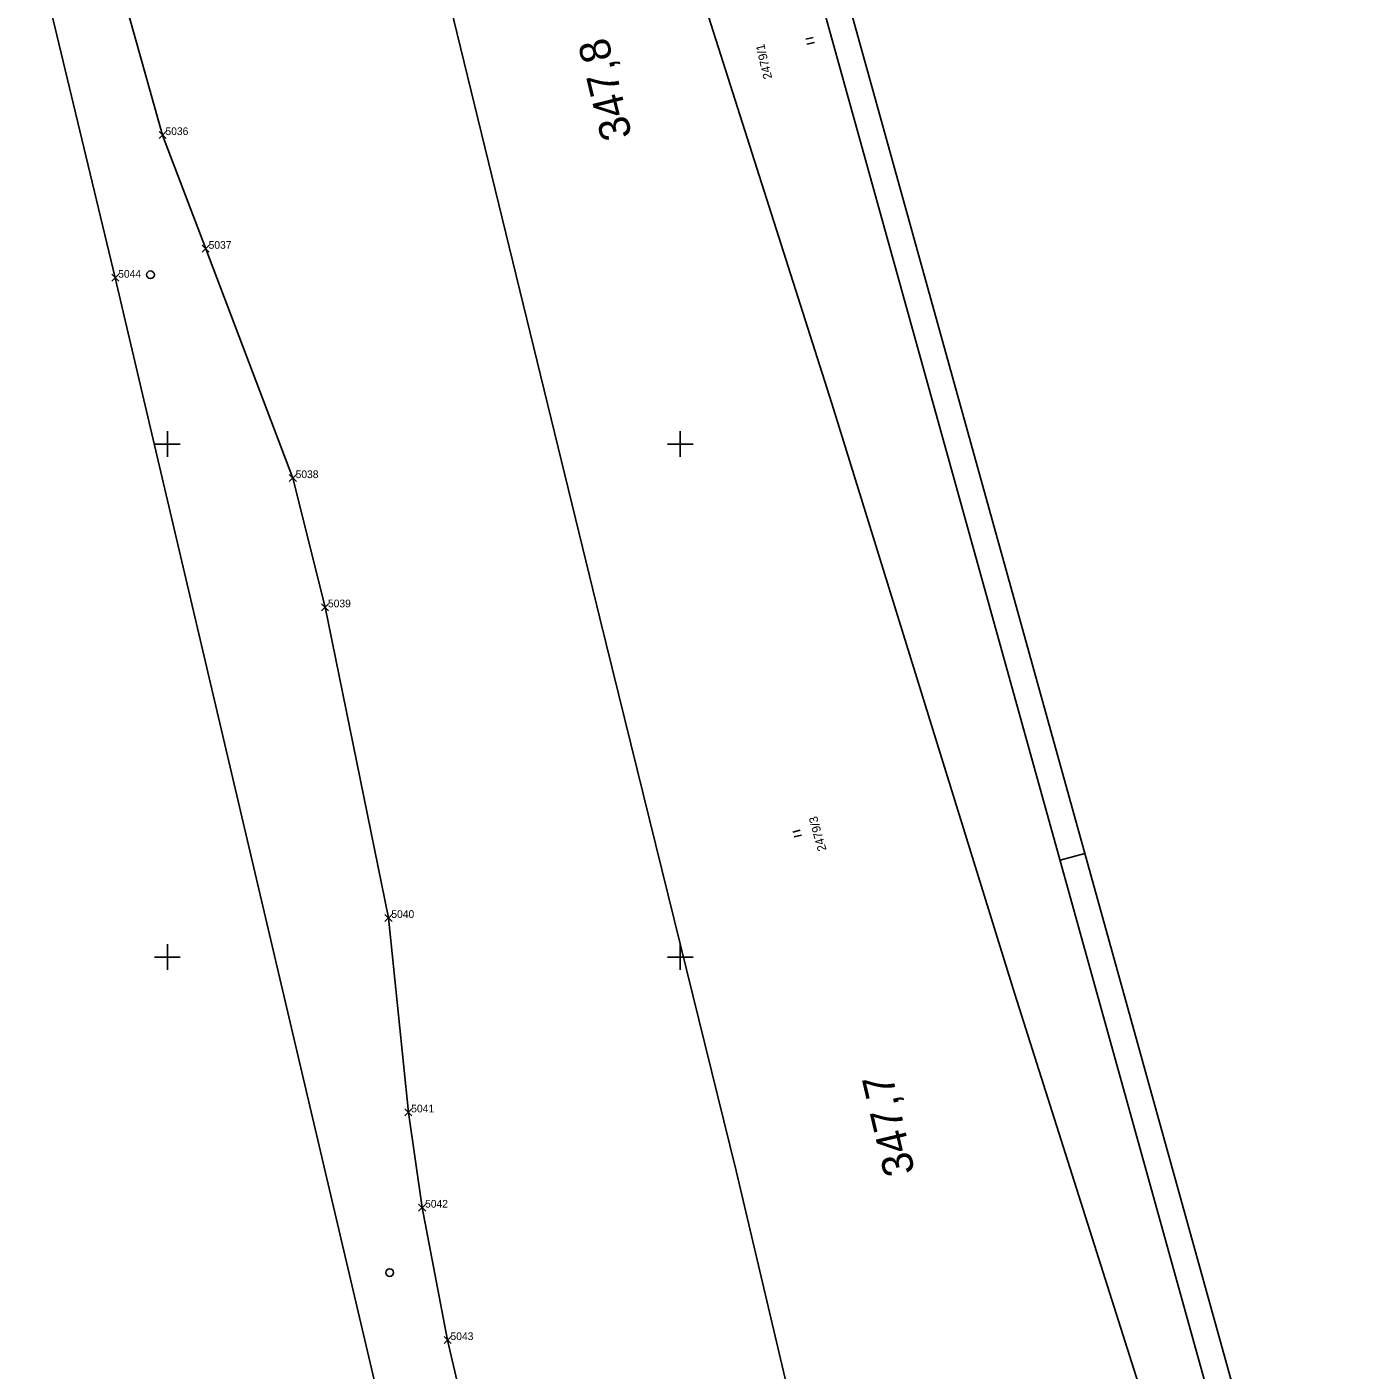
# Model space of a CAD drawing. Extents: x -821172 to -820632, y -1070921 to -1069931.
# Drawn here: x -820763.7 to -820632.5, y -1070790.2 to -1070659.4 of the extents above; entities that cross this region are included whole.
import ezdxf

# ---------------------------------------------------------------- set-up
doc = ezdxf.new("R2010")
doc.units = 0
for name, color, linetype in [('Ram', 7, 'Continuous'), ('Sit', 7, 'Continuous'), ('Sttaniceni a namezniky', 7, 'Continuous'), ('VB_bod_DZ', 7, 'Continuous'), ('Vrstva 52', 7, 'Continuous'), ('Vrstva 53', 7, 'Continuous'), ('Vrstva 55', 7, 'Continuous'), ('Vrstva 57', 7, 'Continuous'), ('Vrstva 59', 7, 'Continuous')]:
    doc.layers.add(name, color=color, linetype=linetype)

msp = doc.modelspace()

# ---------------------------------------------------------------- linework, layer by layer
at = {"layer": 'Ram'}
msp.add_line((-820660.57, -1070739.89), (-820662.98, -1070740.56), dxfattribs=at)
for points in [[(-820857.35, -1070031.72), (-820632.46, -1070841.06)], [(-820859.09, -1070034.8), (-820635.54, -1070839.32), (-820916.88, -1070917.49)]]:
    msp.add_lwpolyline(points, dxfattribs=at)
at = {"layer": 'Sit'}
for p, q in [((-820750, -1070698.75), (-820750, -1070700)), ((-820700, -1070698.75), (-820700, -1070700)), ((-820751.25, -1070700), (-820750, -1070700)), ((-820748.75, -1070700), (-820750, -1070700)), ((-820750, -1070701.25), (-820750, -1070700)), ((-820701.25, -1070700), (-820700, -1070700)), ((-820698.75, -1070700), (-820700, -1070700)), ((-820700, -1070701.25), (-820700, -1070700)), ((-820751.25, -1070750), (-820750, -1070750)), ((-820750, -1070748.75), (-820750, -1070750)), ((-820748.75, -1070750), (-820750, -1070750)), ((-820750, -1070751.25), (-820750, -1070750)), ((-820701.25, -1070750), (-820700, -1070750)), ((-820700, -1070748.75), (-820700, -1070750)), ((-820698.75, -1070750), (-820700, -1070750)), ((-820700, -1070751.25), (-820700, -1070750))]:
    msp.add_line(p, q, dxfattribs=at)
at = {"layer": 'Sttaniceni a namezniky'}
for centre in [(-820751.65, -1070683.5), (-820728.33, -1070780.74)]:
    msp.add_circle(centre, 0.375, dxfattribs=at)
at = {"layer": 'VB_bod_DZ'}
for p, q in [((-820750.81, -1070670.23), (-820750.13, -1070669.55)), ((-820750.13, -1070670.23), (-820750.81, -1070669.55)), ((-820746.61, -1070681.31), (-820745.92, -1070680.62)), ((-820745.92, -1070681.31), (-820746.61, -1070680.62)), ((-820755.43, -1070684.13), (-820754.74, -1070683.45)), ((-820754.74, -1070684.13), (-820755.43, -1070683.45)), ((-820738.12, -1070703.66), (-820737.43, -1070702.97)), ((-820737.43, -1070703.66), (-820738.12, -1070702.97)), ((-820734.97, -1070716.25), (-820734.29, -1070715.56)), ((-820734.29, -1070716.25), (-820734.97, -1070715.56)), ((-820728.79, -1070746.52), (-820728.1, -1070745.84)), ((-820728.1, -1070746.52), (-820728.79, -1070745.84)), ((-820726.86, -1070765.48), (-820726.17, -1070764.79)), ((-820726.17, -1070765.48), (-820726.86, -1070764.79)), ((-820725.51, -1070774.76), (-820724.82, -1070774.07)), ((-820724.82, -1070774.76), (-820725.51, -1070774.07)), ((-820723.02, -1070787.66), (-820722.34, -1070786.97)), ((-820722.34, -1070787.66), (-820723.02, -1070786.97))]:
    msp.add_line(p, q, dxfattribs=at)
at = {"layer": 'Vrstva 52'}
msp.add_lwpolyline([(-820753.84, -1070657.98), (-820750.47, -1070669.89), (-820746.26, -1070680.97), (-820737.78, -1070703.32), (-820734.63, -1070715.91), (-820728.44, -1070746.18), (-820726.51, -1070765.13), (-820725.16, -1070774.41), (-820722.68, -1070787.32), (-820717.67, -1070808.86), (-820710.81, -1070838.96), (-820718.49, -1070840.82), (-820729.1, -1070794.38), (-820755.08, -1070683.79), (-820766.7, -1070635.67)], dxfattribs=at)
at = {"layer": 'Vrstva 53'}
msp.add_lwpolyline([(-820720.44, -1070572.46), (-820743.88, -1070569.76), (-820732.22, -1070617.16), (-820718.37, -1070673.87), (-820707.85, -1070716.96), (-820694.56, -1070770.81), (-820679.24, -1070835.68), (-820677.73, -1070841.82), (-820675.61, -1070850.43)], dxfattribs=at)
at = {"layer": 'Vrstva 55'}
for points in [[(-820720.44, -1070572.46), (-820743.88, -1070569.76), (-820732.22, -1070617.16), (-820718.37, -1070673.87), (-820707.85, -1070716.96), (-820694.56, -1070770.81), (-820679.24, -1070835.68), (-820675.61, -1070850.43)], [(-820643.09, -1070841.4), (-820651.05, -1070805.08), (-820667.4, -1070753.6), (-820685.24, -1070696.04), (-820706.9, -1070628.02), (-820713.28, -1070601.74), (-820720.44, -1070572.46)]]:
    msp.add_lwpolyline(points, dxfattribs=at)
at = {"layer": 'Vrstva 59'}
for p, q in [((-820687.03, -1070660.38), (-820687.76, -1070660.55)), ((-820686.91, -1070660.87), (-820687.65, -1070661.04)), ((-820688.3, -1070737.62), (-820689.03, -1070737.81)), ((-820688.17, -1070738.1), (-820688.9, -1070738.29))]:
    msp.add_line(p, q, dxfattribs=at)

# ---------------------------------------------------------------- texts
at = {"layer": 'Sttaniceni a namezniky'}
for s, rotation, p in [('347,8', 103.8826, (-820704.69, -1070669.98)), ('347,7', 103.1734, (-820677.11, -1070770.95))]:
    msp.add_text(s, height=3, rotation=rotation, dxfattribs=at).set_placement(p)
at = {"layer": 'VB_bod_DZ'}
for s, p in [(' 5036', (-820750.47, -1070669.89)), (' 5037', (-820746.26, -1070680.97)), (' 5044', (-820755.08, -1070683.79)), (' 5038', (-820737.78, -1070703.32)), (' 5039', (-820734.63, -1070715.91)), (' 5040', (-820728.45, -1070746.18)), (' 5041', (-820726.51, -1070765.13)), (' 5042', (-820725.16, -1070774.41)), (' 5043', (-820722.68, -1070787.32))]:
    msp.add_text(s, height=0.75, dxfattribs=at).set_placement(p)
at = {"layer": 'Vrstva 57'}
for s, rotation, p in [('2479/1', 103, (-820691.04, -1070664.33)), ('2479/3', 105.5289, (-820685.74, -1070739.55))]:
    msp.add_text(s, height=0.85, rotation=rotation, dxfattribs=at).set_placement(p)

doc.saveas('drawing.dxf')
